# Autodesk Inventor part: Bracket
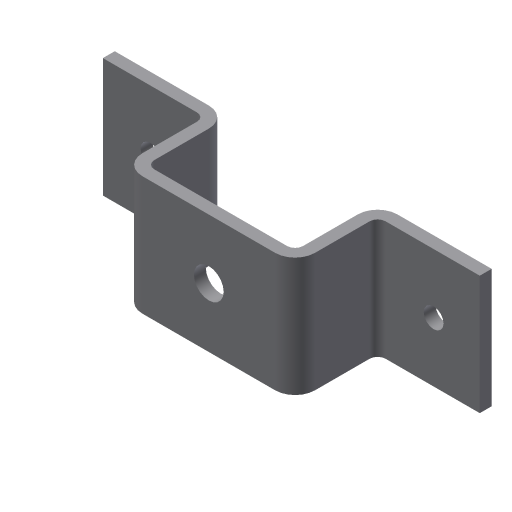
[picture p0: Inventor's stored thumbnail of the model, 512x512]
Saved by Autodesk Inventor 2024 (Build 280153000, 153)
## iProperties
Created: 2010-05
Part Number: Bracket
Document SubType Name: Modeling
Designer: CADSoft
Density: 1 g/cm^3
Material: Generic
Appearance: Default
Author: CADSoft
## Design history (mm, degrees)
sketch "Sketch1"
  geometry: L1 (-476.866, 0)-(-189.366, 0); L2 (-189.366, 0)-(-189.366, -208); L3 (-189.366, -208)-(185.634, -208); L4 (185.634, -208)-(185.634, 0); L5 (185.634, 0)-(473.134, 0); L6 (473.134, 0)-(473.134, -30); L7 (473.134, -30)-(215.634, -30); L8 (215.634, -30)-(215.634, -238); L9 (215.634, -238)-(-219.366, -238); L10 (-219.366, -238)-(-219.366, -30); L11 (-219.366, -30)-(-476.866, -30); L12 (-476.866, -30)-(-476.866, 0); 1 further point
  constraints: 24 end point, 8 parallel, 5 equal length, 1 collinear, 1 horizontal, 1 horizontal alignment, 1 perpendicular
  dimensions: "d0" = 950 distance between parallel lines of L6 L12; "d1" = 238 distance between parallel lines of L1 L9; "d2" = 30 distance of L5.end L6.end; "d3" = 30 distance between parallel lines of L9 L3; "d4" = 30 distance between parallel lines of L4 L8; "d5" = 435 distance of L8.end L9.end
extrude "Extrusion1" new body sketch "Sketch1" stored distance "d6" = 300; taper "d7" = 0 deg
fillet "Fillet1" dims "d8" = 20
fillet "Fillet2" dims "d9" = 50
hole "Hole1" diameter "d12" = 75; stored, may be unused: countersink angle "d16" = 90 deg, drill point angle "d18" = 118 deg; dims "d10" = 150, "d11" = 217.5, "d13" = 6, "d14" = 4, "d15" = 2, "d17" = 8
hole "Hole2" diameter "d21" = 50; stored, may be unused: countersink angle "d25" = 90 deg, drill point angle "d27" = 118 deg; dims "d19" = 150, "d20" = 120, "d22" = 6, "d23" = 4, "d24" = 2, "d26" = 8
mirror "Mirror1"
body "Solid1"
